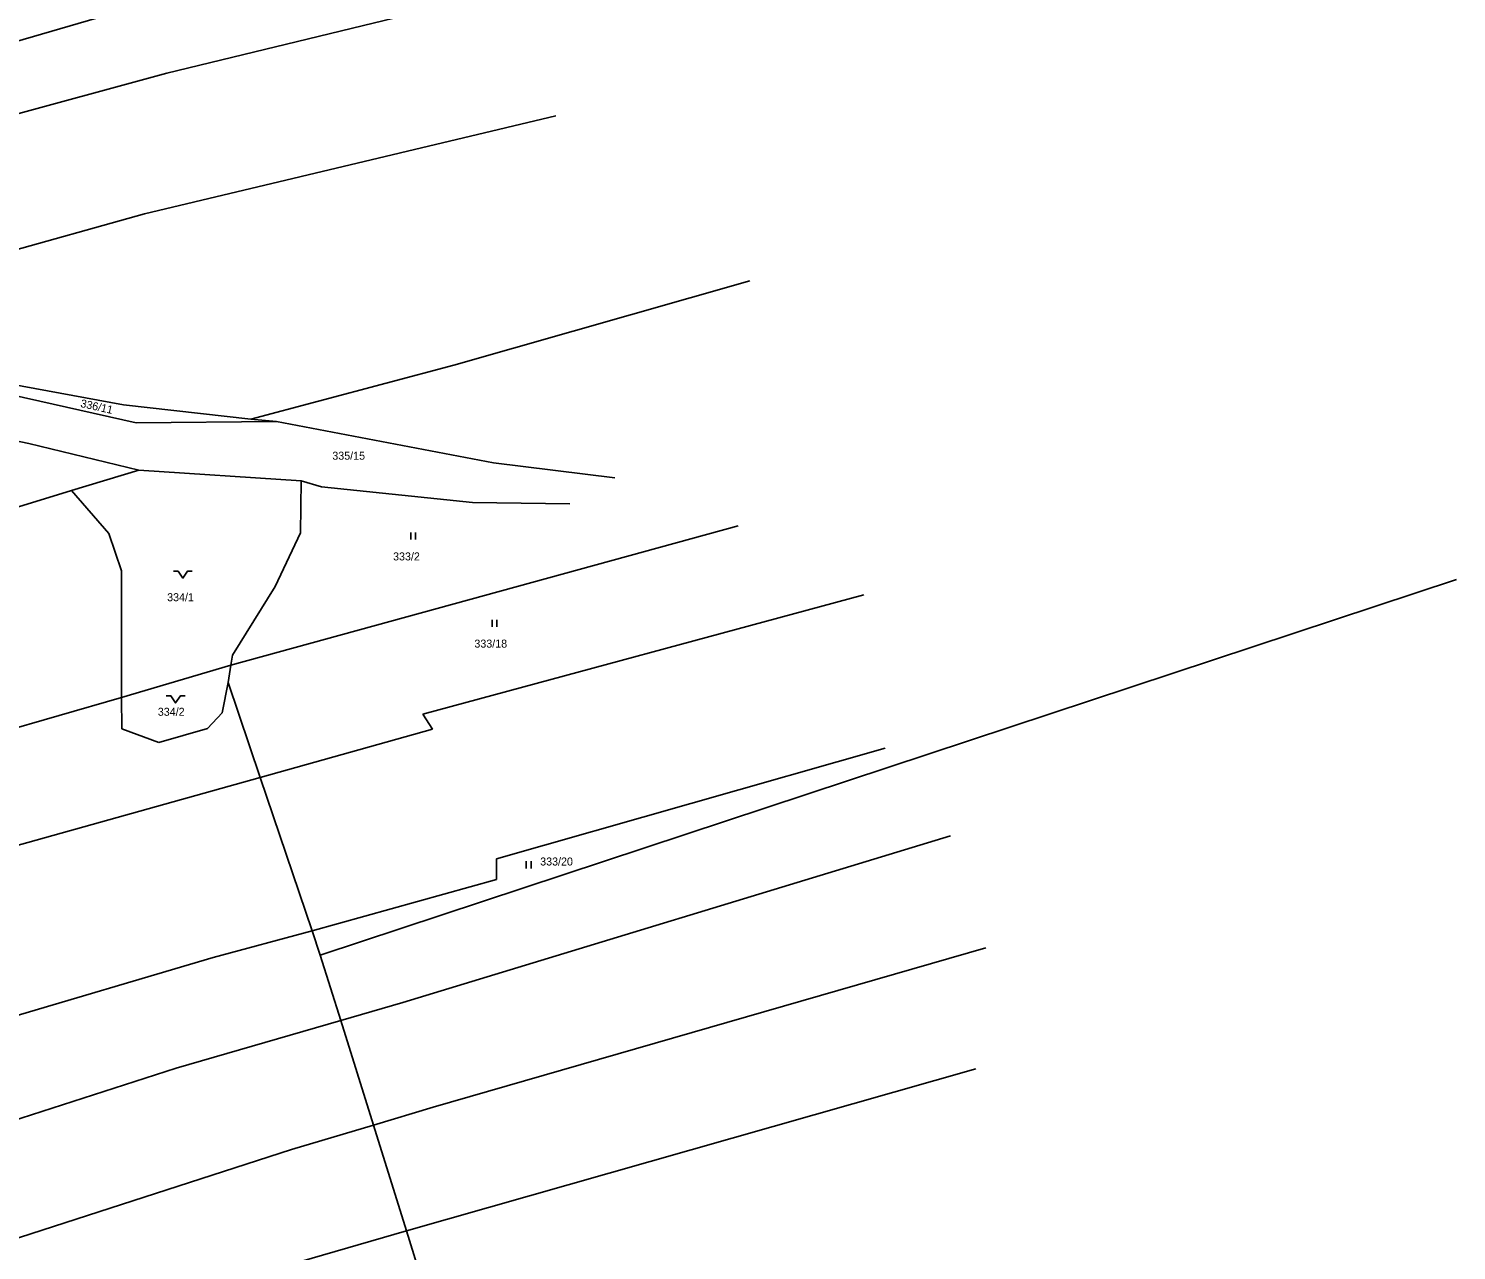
# Model space of a CAD drawing. Extents: x -762263 to -760336, y -1154405 to -1152076.
# Drawn here: x -760991.9 to -760688.7, y -1152889.5 to -1152630.1 of the extents above; entities that cross this region are included whole.
import ezdxf

# ---------------------------------------------------------------- set-up
doc = ezdxf.new("R2010")
doc.units = 0
for name, color, linetype in [('Vrstva 1', 7, 'Continuous'), ('Vrstva 18', 7, 'Continuous'), ('Vrstva 25', 7, 'Continuous'), ('Vrstva 6', 7, 'Continuous')]:
    doc.layers.add(name, color=color, linetype=linetype)

msp = doc.modelspace()

# ---------------------------------------------------------------- linework, layer by layer
at = {"layer": 'Vrstva 1'}
for p, q in [((-761022.68, -1152701.74), (-760969.06, -1152713.8)), ((-760991.86, -1152718.2), (-761029.24, -1152710.24)), ((-760969.06, -1152713.8), (-760939.25, -1152713.56)), ((-760939.25, -1152713.56), (-760893.13, -1152722.27)), ((-760968.45, -1152723.84), (-760991.86, -1152718.2)), ((-760982.8, -1152728.18), (-760968.45, -1152723.84)), ((-760934.03, -1152726.14), (-760968.45, -1152723.84)), ((-760893.13, -1152722.27), (-760867.4, -1152725.52)), ((-761042.6, -1152746.5), (-760982.8, -1152728.18)), ((-760982.8, -1152728.18), (-760974.82, -1152737.31)), ((-760934.03, -1152726.14), (-760934.13, -1152737.19)), ((-760929.7, -1152727.4), (-760934.03, -1152726.14)), ((-760897.6, -1152730.7), (-760929.7, -1152727.4)), ((-760876.95, -1152731), (-760897.6, -1152730.7)), ((-760934.13, -1152737.19), (-760939.55, -1152748.58)), ((-760972.19, -1152745.21), (-760974.82, -1152737.31)), ((-760972.19, -1152745.21), (-760972.13, -1152772.12)), ((-760948.56, -1152763.17), (-760939.55, -1152748.58)), ((-760929.96, -1152826.79), (-760688.65, -1152747.09)), ((-760948.92, -1152765.25), (-760948.56, -1152763.17)), ((-760949.54, -1152768.91), (-760948.92, -1152765.25)), ((-760950.79, -1152775.38), (-760949.54, -1152768.91)), ((-760949.54, -1152768.91), (-760942.71, -1152789.09)), ((-760972.13, -1152772.12), (-760972.12, -1152778.77)), ((-760953.91, -1152778.68), (-760950.79, -1152775.38)), ((-760972.12, -1152778.77), (-760964.23, -1152781.68)), ((-760964.23, -1152781.68), (-760953.91, -1152778.68)), ((-760942.71, -1152789.09), (-760931.7, -1152821.63)), ((-760931.7, -1152821.63), (-760929.96, -1152826.79)), ((-760925.6, -1152840.73), (-760929.96, -1152826.79)), ((-760925.6, -1152840.73), (-760918.67, -1152862.91)), ((-760918.67, -1152862.91), (-760911.65, -1152885.38)), ((-760902.55, -1152914.51), (-760911.65, -1152885.38))]:
    msp.add_line(p, q, dxfattribs=at)
at = {"layer": 'Vrstva 25'}
for p, q in [((-760910.74, -1152738.59), (-760910.74, -1152737.09)), ((-760909.74, -1152738.59), (-760909.74, -1152737.09)), ((-760893.46, -1152757.1), (-760893.46, -1152755.6)), ((-760892.46, -1152757.1), (-760892.46, -1152755.6)), ((-760886.19, -1152808.4), (-760886.19, -1152806.9)), ((-760885.19, -1152808.4), (-760885.19, -1152806.9))]:
    msp.add_line(p, q, dxfattribs=at)
for points in [[(-760961.13, -1152745.27), (-760960.13, -1152745.27), (-760959.13, -1152746.77), (-760958.13, -1152745.27), (-760957.13, -1152745.27)], [(-760962.66, -1152771.77), (-760961.66, -1152771.77), (-760960.66, -1152773.27), (-760959.66, -1152771.77), (-760958.66, -1152771.77)]]:
    msp.add_lwpolyline(points, dxfattribs=at)
at = {"layer": 'Vrstva 6'}
for p, q in [((-761041.29, -1152646.52), (-760934.96, -1152615.47)), ((-760962.51, -1152639.61), (-760877.33, -1152618.88)), ((-761065, -1152667.4), (-760962.51, -1152639.61)), ((-760967.3, -1152669.41), (-760879.92, -1152648.62)), ((-761020.26, -1152684.25), (-760967.3, -1152669.41)), ((-760901.56, -1152701.59), (-760838.69, -1152683.64)), ((-760971.71, -1152710.02), (-761019.09, -1152701.32)), ((-760944.72, -1152713.04), (-760901.56, -1152701.59)), ((-760971.71, -1152710.02), (-760944.72, -1152713.04)), ((-760944.72, -1152713.04), (-760939.25, -1152713.56)), ((-760948.92, -1152765.25), (-760841.23, -1152735.69)), ((-760908.19, -1152775.63), (-760814.49, -1152750.33)), ((-760948.92, -1152765.25), (-760972.13, -1152772.12)), ((-761098.07, -1152808.56), (-760972.13, -1152772.12)), ((-760906.1, -1152778.85), (-760908.19, -1152775.63)), ((-760942.71, -1152789.09), (-760906.1, -1152778.85)), ((-760892.52, -1152806.39), (-760809.96, -1152782.89)), ((-761089.99, -1152830.31), (-760942.71, -1152789.09)), ((-760912.4, -1152836.87), (-760796.08, -1152801.49)), ((-760892.52, -1152810.73), (-760892.52, -1152806.39)), ((-760931.7, -1152821.63), (-760892.52, -1152810.73)), ((-760952.7, -1152827.35), (-760931.7, -1152821.63)), ((-761076.01, -1152863.8), (-760952.7, -1152827.35)), ((-760788.62, -1152825.25), (-760905.97, -1152859.11)), ((-760925.6, -1152840.73), (-760912.4, -1152836.87)), ((-760960.52, -1152850.8), (-760925.6, -1152840.73)), ((-760997.88, -1152862.82), (-760960.52, -1152850.8)), ((-760911.65, -1152885.38), (-760790.7, -1152850.98)), ((-760918.67, -1152862.91), (-760905.97, -1152859.11)), ((-760936.04, -1152868.11), (-760918.67, -1152862.91)), ((-761000.71, -1152888.98), (-760936.04, -1152868.11)), ((-760968.87, -1152901.87), (-760911.65, -1152885.38))]:
    msp.add_line(p, q, dxfattribs=at)

# ---------------------------------------------------------------- texts
at = {"layer": 'Vrstva 18'}
msp.add_text('336/11', height=1.7, rotation=347.4989, dxfattribs=at).set_placement((-760980.985, -1152710.431))
for s, p in [('335/15', (-760927.392, -1152721.64)), ('333/2', (-760914.488, -1152743.02)), ('334/1', (-760962.469, -1152751.68)), ('333/18', (-760897.216, -1152761.53)), ('334/2', (-760964.451, -1152776)), ('333/20', (-760883.244, -1152807.79))]:
    msp.add_text(s, height=1.7, dxfattribs=at).set_placement(p)

doc.saveas('drawing.dxf')
